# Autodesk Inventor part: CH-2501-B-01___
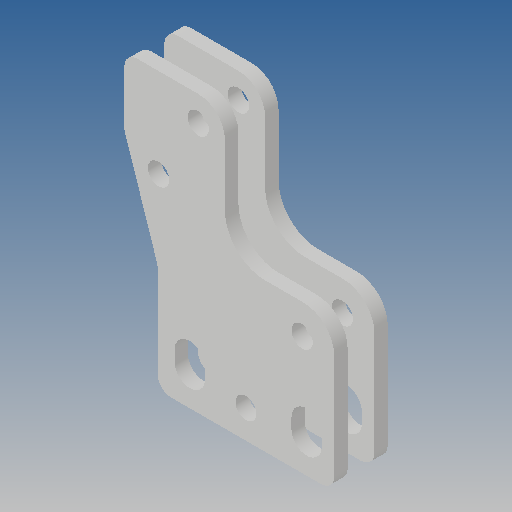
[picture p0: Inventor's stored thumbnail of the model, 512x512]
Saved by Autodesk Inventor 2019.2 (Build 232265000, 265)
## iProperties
Created: 2012-09
Part Number: CH-2501-B-01___
Material: Ogólny
Document SubType Name: Modeling
Designer: CADENGINEERING4
Density: 1 g/cm^3
Appearance: Domyślna
Author: CADENGINEERING4
Revision Number: ÈÎºÎ
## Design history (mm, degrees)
feature "NONE" [ÊäÈë]
feature "ÊäÈë2"
node "Bryła1"
node "Bryła2"
